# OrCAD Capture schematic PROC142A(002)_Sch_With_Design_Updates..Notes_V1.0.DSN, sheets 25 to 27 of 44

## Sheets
25 24. PHY CLK & LED DRIVER: size C; title: ETHERNET PHY CLOCK BUFFER & LED DRIVER
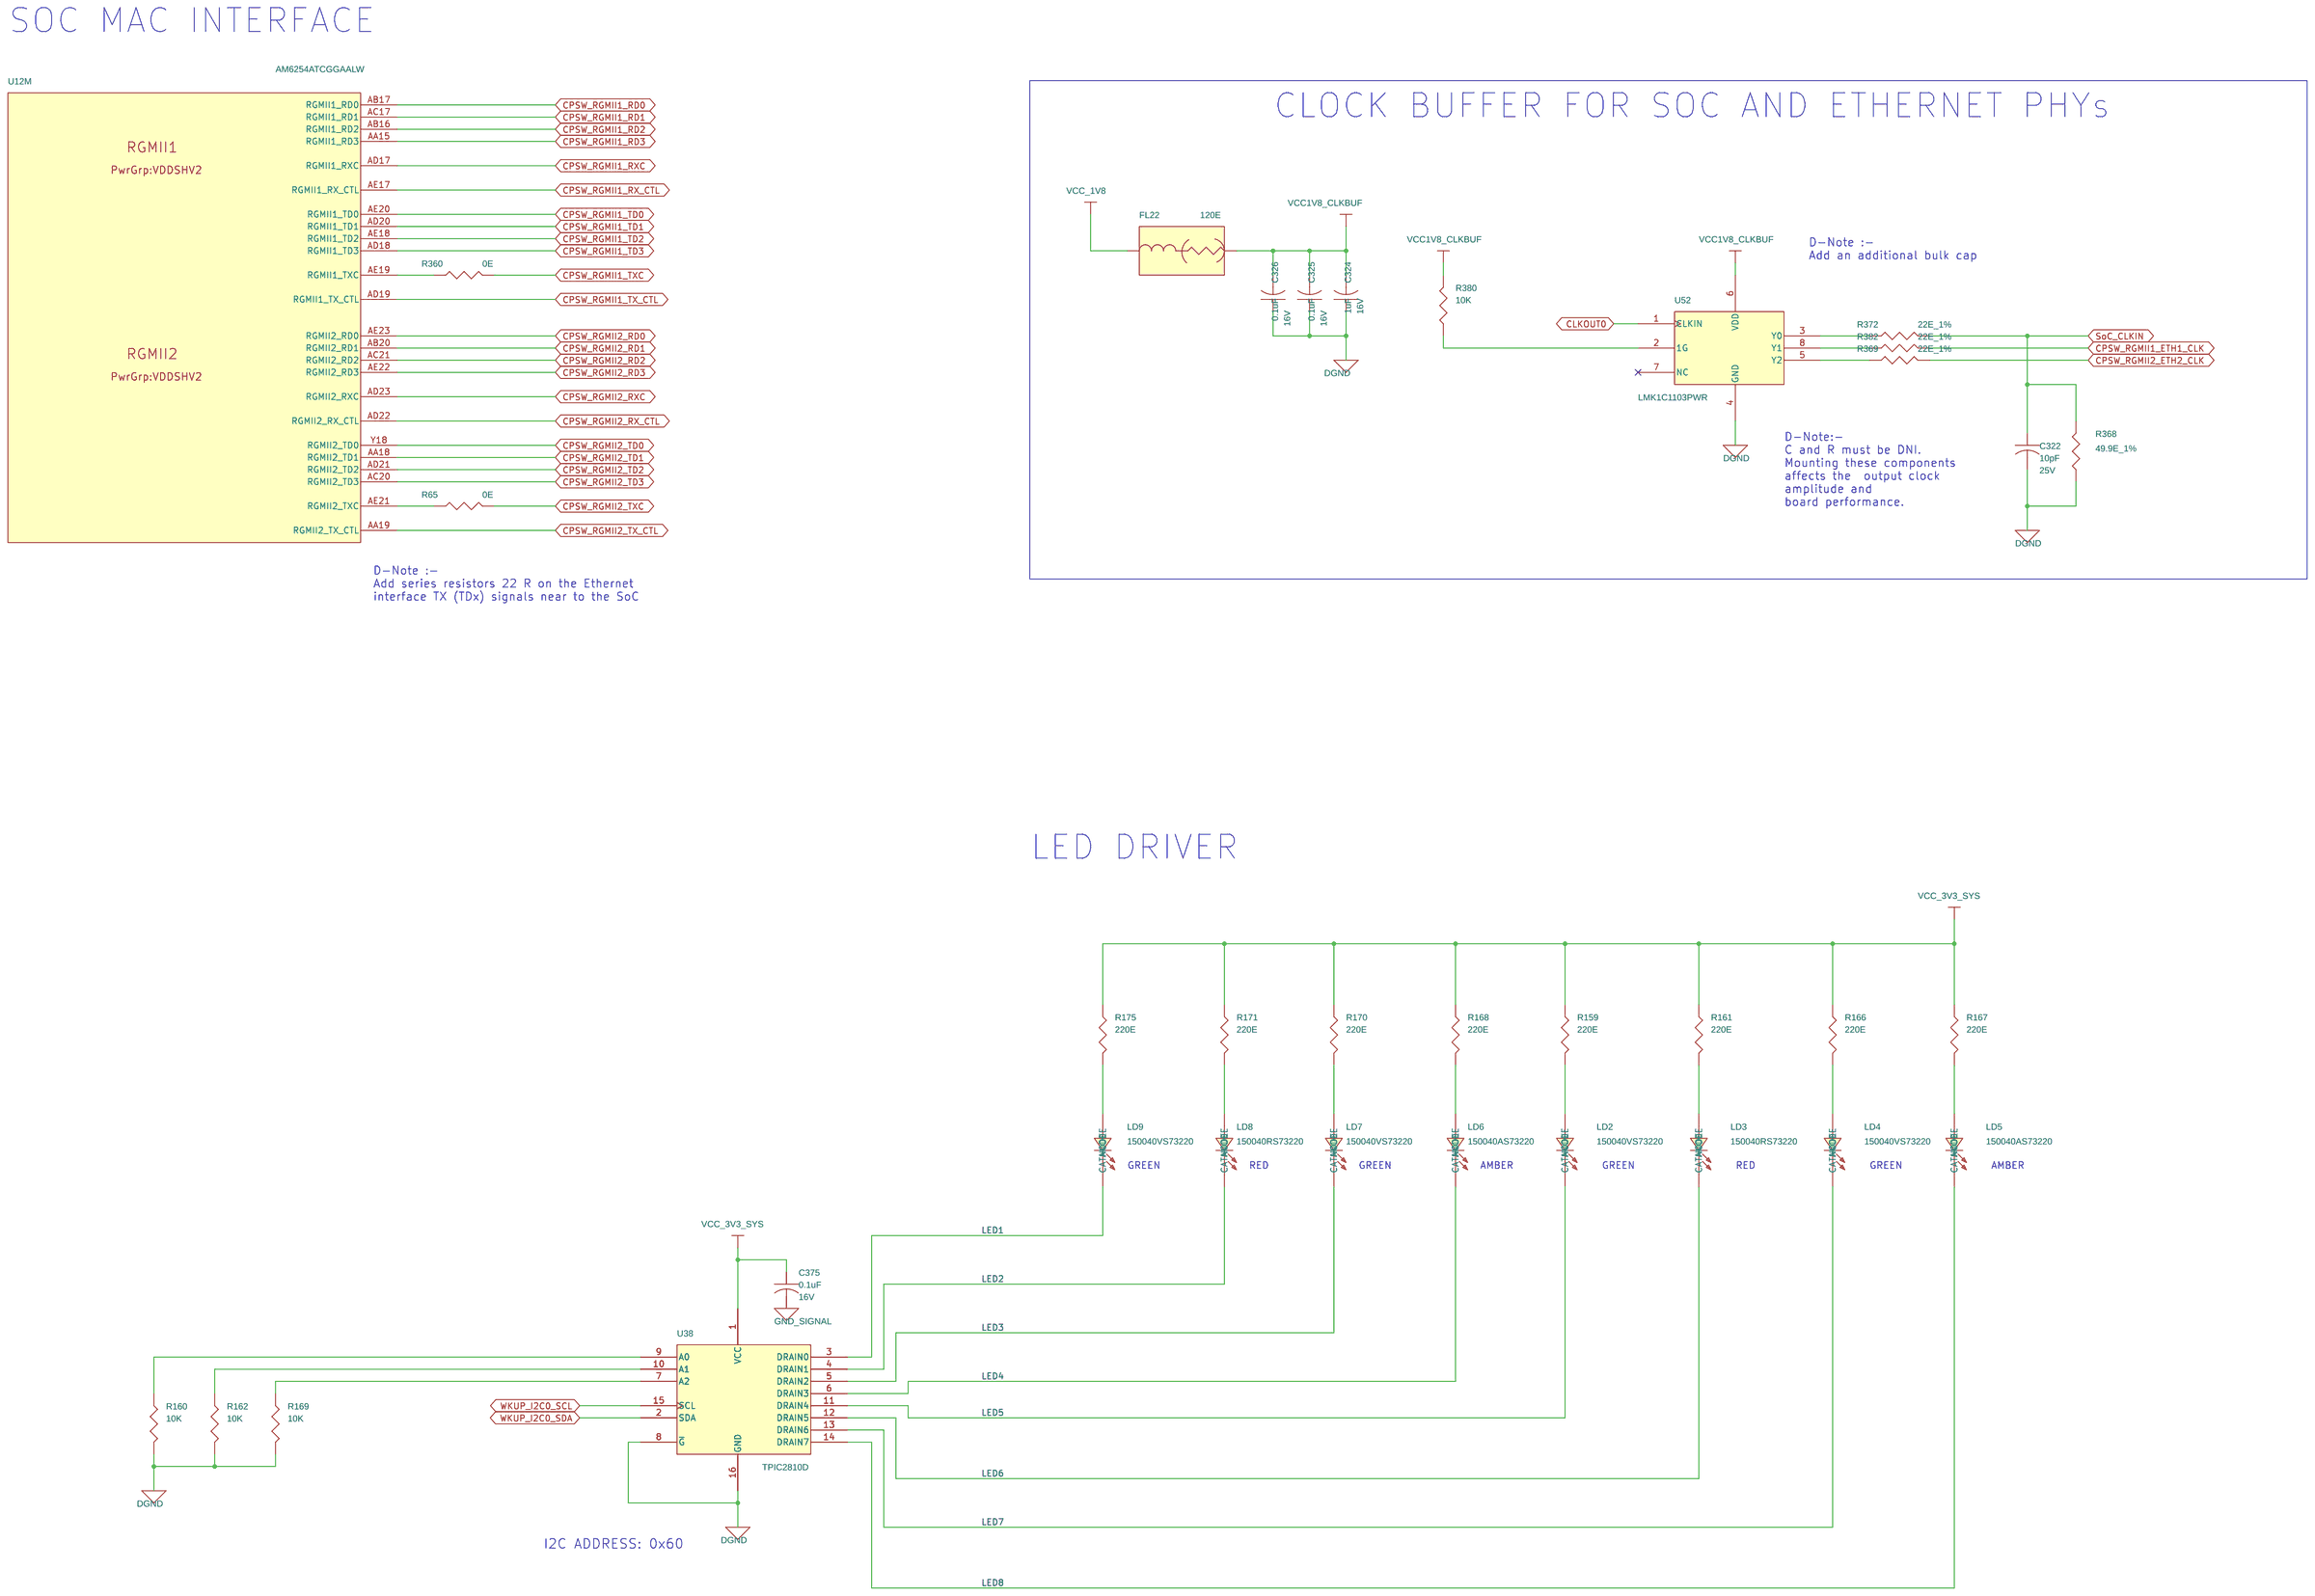
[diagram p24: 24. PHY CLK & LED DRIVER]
26 25. TEST AUTOMATION: size C; title: TEST AUTOMATION
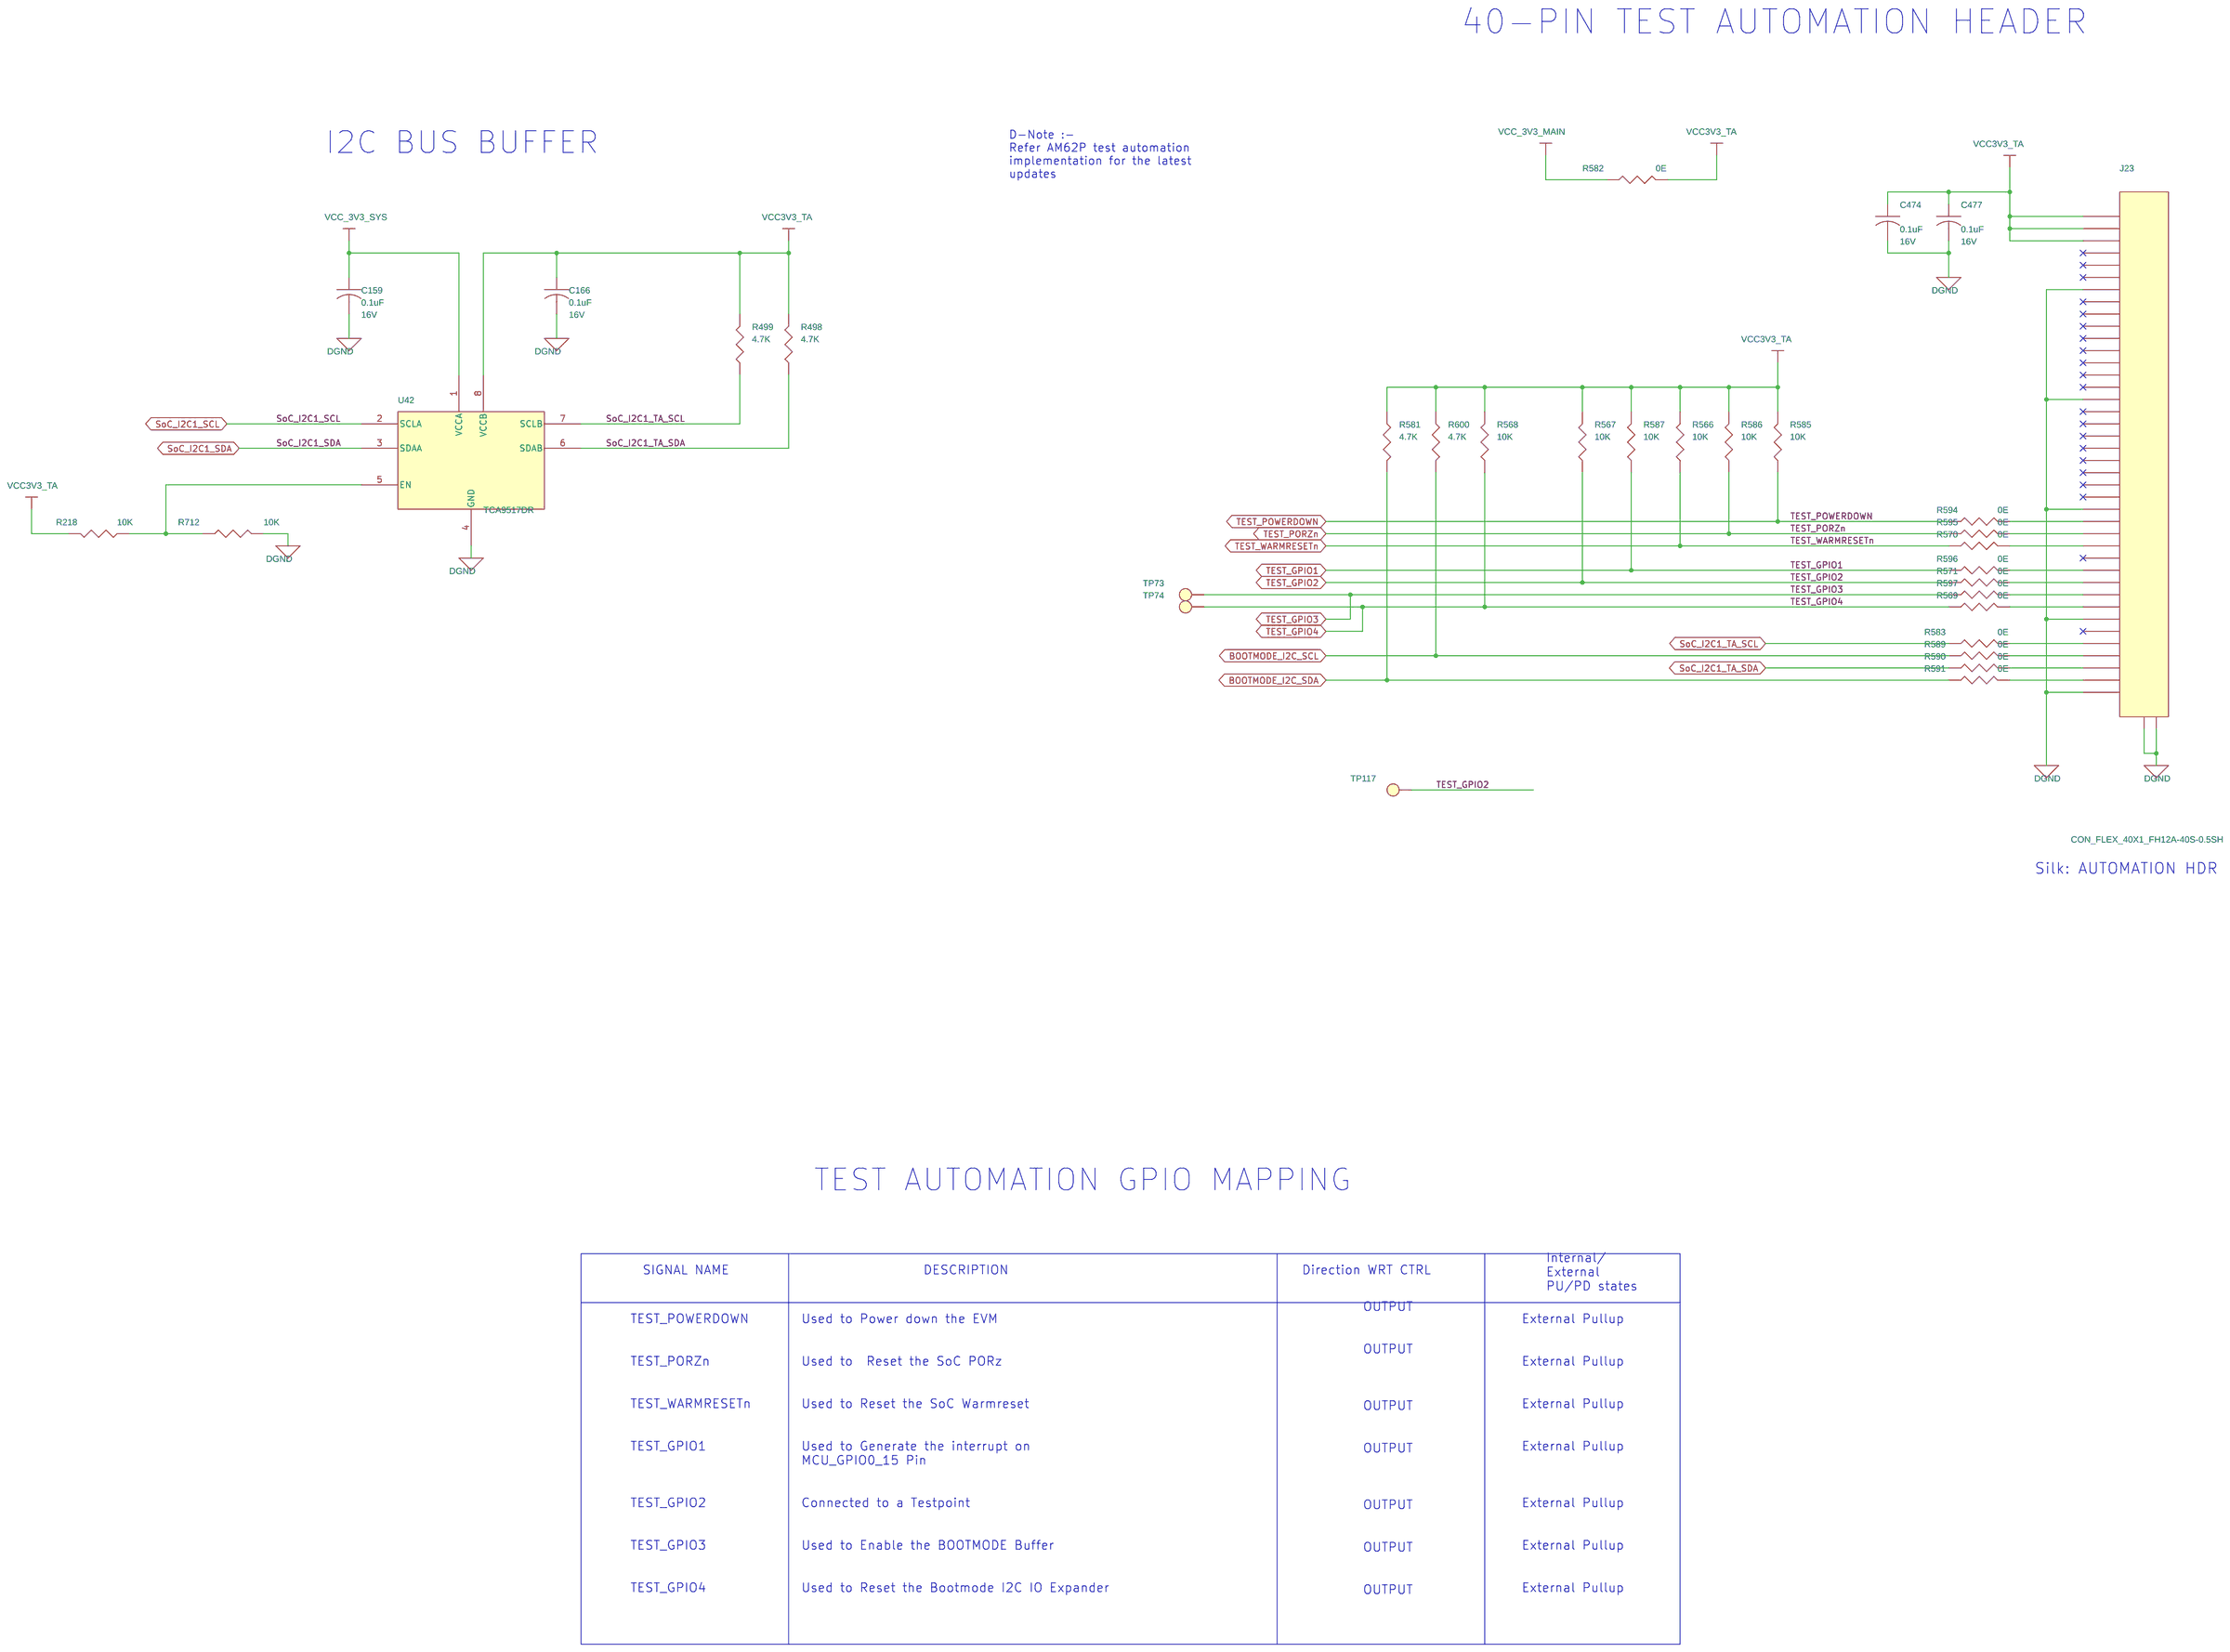
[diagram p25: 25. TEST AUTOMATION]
27 26. BOOT MODE BUFFER & SWITCHES: size C; title: BOOT MODE BUFFER & SWITCHES
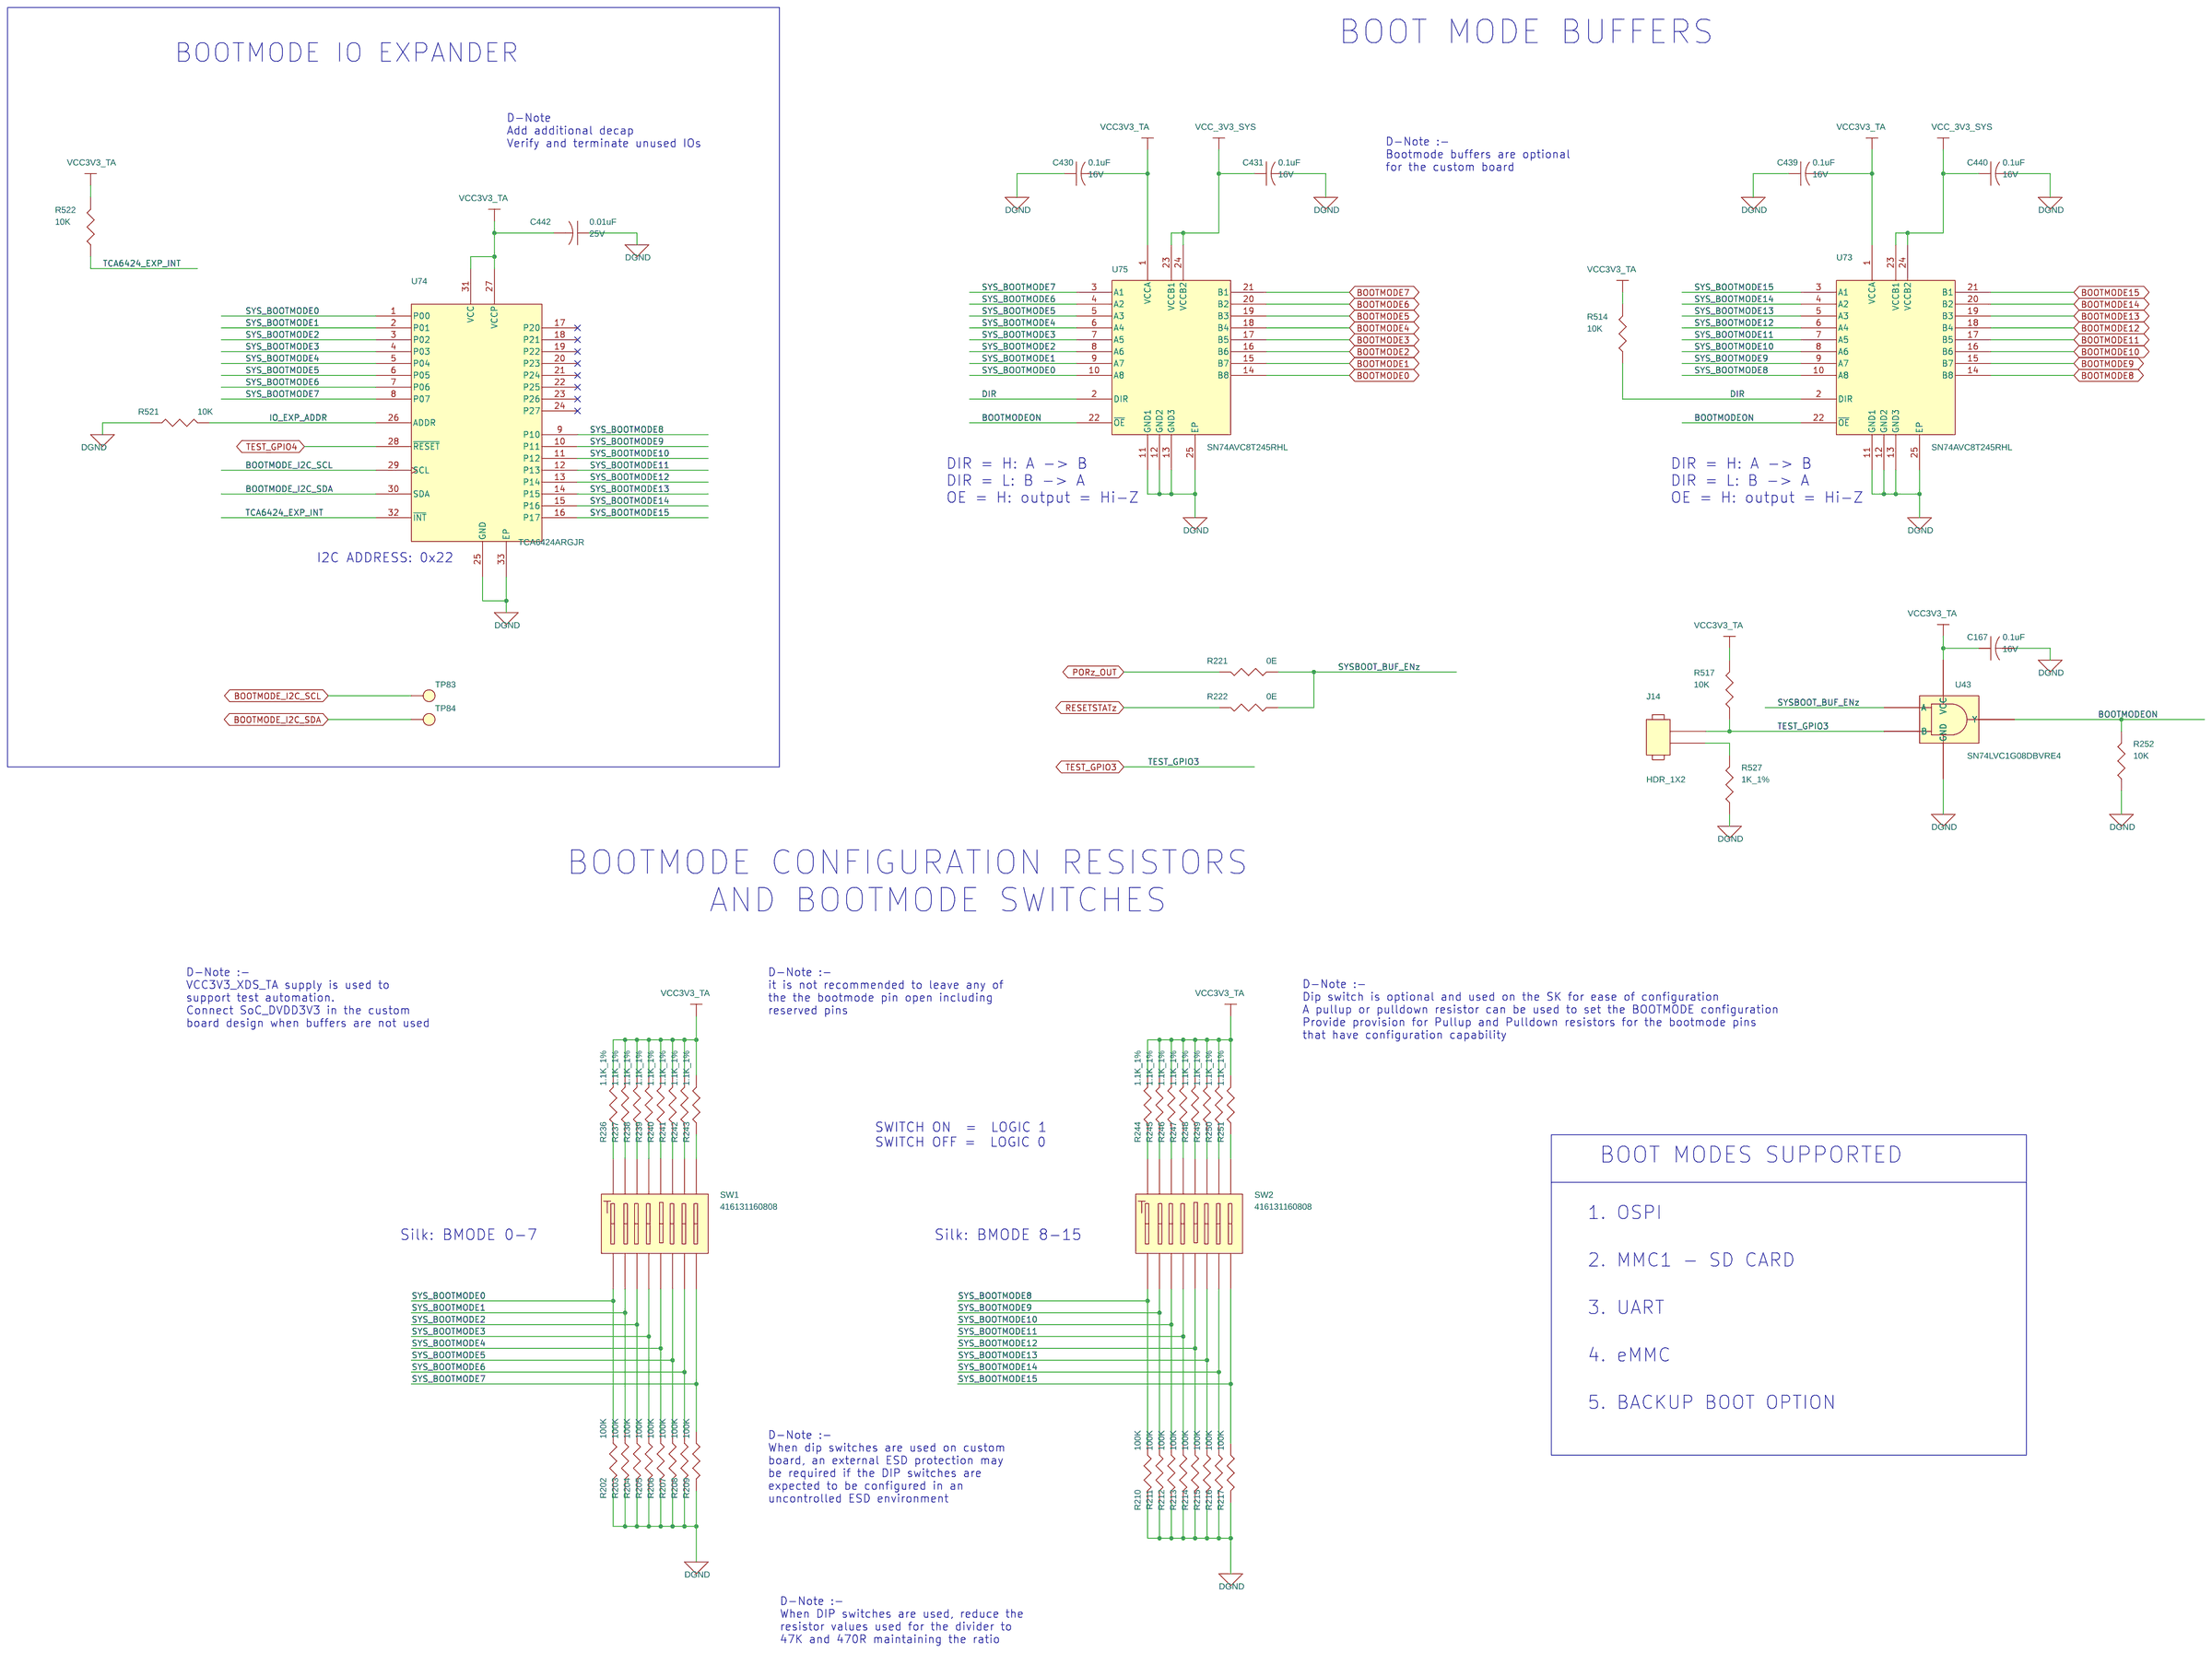
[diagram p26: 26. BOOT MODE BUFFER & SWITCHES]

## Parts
sheet 24. PHY CLK & LED DRIVER
C322  10pF  [CAP0201_0-5]
C324  1uF  [CAP0201_0-5]
C325  0.1uF  [CAP0201_0-5]
C326  0.1uF  [CAP0201_0-5]
C375  0.1uF  [CAP0201_0-5]
FL22  120E  [EMIFIL_BLM15A_0402_0-6]
LD2  150040VS73220  [LED_150040GS73220_40X20_SMD_0-4]
LD3  150040RS73220  [LED_150040GS73220_40X20_SMD_0-4]
LD4  150040VS73220  [LED_150040GS73220_40X20_SMD_0-4]
LD5  150040AS73220  [LED_150040GS73220_40X20_SMD_0-4]
LD6  150040AS73220  [LED_150040GS73220_40X20_SMD_0-4]
LD7  150040VS73220  [LED_150040GS73220_40X20_SMD_0-4]
LD8  150040RS73220  [LED_150040GS73220_40X20_SMD_0-4]
LD9  150040VS73220  [LED_150040GS73220_40X20_SMD_0-4]
R65  0E  [RES0402_0-5]
R159  220E  [RES0402_0-5]
R160  10K  [RES0201_0-5]
R161  220E  [RES0402_0-5]
R162  10K  [RES0201_0-5]
R166  220E  [RES0402_0-5]
R167  220E  [RES0402_0-5]
R168  220E  [RES0402_0-5]
R169  10K  [RES0201_0-5]
R170  220E  [RES0402_0-5]
R171  220E  [RES0402_0-5]
R175  220E  [RES0402_0-5]
R360  0E  [RES0402_0-5]
R368  49.9E_1%  [RES0402_0-5]
R369  22E_1%  [RES0201_0-5]
R372  22E_1%  [RES0201_0-5]
R380  10K  [RES0201_0-5]
R382  22E_1%  [RES0201_0-5]
U38  TPIC2810D  [SOIC16_1-8]
U52  LMK1C1103PWR  [TSSOP8_25-59_125X180_1-2]
sheet 25. TEST AUTOMATION
C159  0.1uF  [CAP0201_0-5]
C166  0.1uF  [CAP0201_0-5]
C474  0.1uF  [CAP0201_0-5]
C477  0.1uF  [CAP0201_0-5]
J23  CON_FLEX_40X1_FH12A-40S-0.5SH  [CON_FLEX40X1_FH12A_S_R_S]
R218  10K  [RES0201_0-5]
R498  4.7K  [RES0201_0-5]
R499  4.7K  [RES0201_0-5]
R566  10K  [RES0201_0-5]
R567  10K  [RES0201_0-5]
R568  10K  [RES0201_0-5]
R569  0E  [RES0402_0-5]
R570  0E  [RES0402_0-5]
R571  0E  [RES0402_0-5]
R581  4.7K  [RES0201_0-5]
R582  0E  [RES0805_0-75]
R583  0E  [RES0402_0-5]
R585  10K  [RES0201_0-5]
R586  10K  [RES0201_0-5]
R587  10K  [RES0201_0-5]
R589  0E  [RES0402_0-5]
R590  0E  [RES0402_0-5]
R591  0E  [RES0402_0-5]
R594  0E  [RES0402_0-5]
R595  0E  [RES0402_0-5]
R596  0E  [RES0402_0-5]
R597  0E  [RES0402_0-5]
R600  4.7K  [RES0201_0-5]
R712  10K  [RES0201_0-5]
TP73  TP20_SMD  [TP20_SMD]
TP74  TP20_SMD  [TP20_SMD]
TP117  TP20_SMD  [TP20_SMD]
U42  TCA9517DR  [SOIC8_1-8]
sheet 26. BOOT MODE BUFFER & SWITCHES
C167  0.1uF  [CAP0201_0-5]
C430  0.1uF  [CAP0201_0-5]
C431  0.1uF  [CAP0201_0-5]
C439  0.1uF  [CAP0201_0-5]
C440  0.1uF  [CAP0201_0-5]
C442  0.01uF  [CAP0201_0-5]
J14  HDR_1X2  [HDR_1X2_90120-0122_S_T_5-6]
R202  100K  [RES0201_0-5]
R203  100K  [RES0201_0-5]
R204  100K  [RES0201_0-5]
R205  100K  [RES0201_0-5]
R206  100K  [RES0201_0-5]
R207  100K  [RES0201_0-5]
R208  100K  [RES0201_0-5]
R209  100K  [RES0201_0-5]
R210  100K  [RES0201_0-5]
R211  100K  [RES0201_0-5]
R212  100K  [RES0201_0-5]
R213  100K  [RES0201_0-5]
R214  100K  [RES0201_0-5]
R215  100K  [RES0201_0-5]
R216  100K  [RES0201_0-5]
R217  100K  [RES0201_0-5]
R221  0E  [RES0201_0-5]
R222  0E  [RES0402_0-5]
R236  1.1K_1%  [RES0201_0-5]
R237  1.1K_1%  [RES0201_0-5]
R238  1.1K_1%  [RES0201_0-5]
R239  1.1K_1%  [RES0201_0-5]
R240  1.1K_1%  [RES0201_0-5]
R241  1.1K_1%  [RES0201_0-5]
R242  1.1K_1%  [RES0201_0-5]
R243  1.1K_1%  [RES0201_0-5]
R244  1.1K_1%  [RES0201_0-5]
R245  1.1K_1%  [RES0201_0-5]
R246  1.1K_1%  [RES0201_0-5]
R247  1.1K_1%  [RES0201_0-5]
R248  1.1K_1%  [RES0201_0-5]
R249  1.1K_1%  [RES0201_0-5]
R250  1.1K_1%  [RES0201_0-5]
R251  1.1K_1%  [RES0201_0-5]
R252  10K  [RES0201_0-5]
R514  10K  [RES0201_0-5]
R517  10K  [RES0201_0-5]
R521  10K  [RES0201_0-5]
R522  10K  [RES0201_0-5]
R527  1K_1%  [RES0402_0-5]
SW1  416131160808  [SW16_416131160808_460X230_SMD_2-7]
SW2  416131160808  [SW16_416131160808_460X230_SMD_2-7]
TP83  TP20_SMD  [TP20_SMD]
TP84  TP20_SMD  [TP20_SMD]
U43  SN74LVC1G08DBVRE4  [SOT23-5]
U73  SN74AVC8T245RHL  [QFN24_19-68_220X140_1]
U74  TCA6424ARGJR  [QFN32_19-68_200X200]
U75  SN74AVC8T245RHL  [QFN24_19-68_220X140_1]
sheet 42. OSCILLATOR
U12  AM6254ATCGGAALW  [BGA425_19-68_510X510_0-7]  (sections A,B,C,D,E,F,G,H,I,J,K,L,M,N,O,P,Q,R)

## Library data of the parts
C322 = CAP: CAP CERAMIC 10pF 25V 5% HI-Q C0G(NP0) 0201; Chkd/date: VASANTHA/081216; Crtd /date: MANIRAJA/081216; Custom_Duty: 15%; Customs_HS_Code: 85322990; Distributor_name: DIGIKEY; Distributor_part_number: 490-13312-1-ND; Footprint Path: Y:\MIS_DATABASE\Library\ALTIUM_TOOL\PCB_FOOTPRINTS\Altium_Footprint_Lib.PcbLib; Height: 0.33MM; Library Path: Y:\MIS_DATABASE\Library\ALTIUM_TOOL\SCHEMATICS_PARTS\MS_DISCRETE_Library.schlib; Mfr_name: MURATA; Mfr_part_number: GJM0335C1E100JB01D; Mistral Part No: 120016120010-R; Package: 0201; Part_type: CAPACITORS\CERAMIC; Project: OCTBTS5200; RoHS: RoHS; Temperature: -55°C+125°C; Tolerance: 5%; Voltage: 25V; Wattage: NA; Weight: 0.33mg; Datasheet: Y:\MIS_DATABASE\DATASHEETS\CAPACITORS\MURATA-GXX-SER_NOV17.PDF
C324 = CAP: CAP CERAMIC 1uF 16V 20% X5R 0201; Chkd/date: MANIRAJA/300520; Crtd /date: ALVY/260520; Custom_Duty: 15%; Customs_HS_Code: 85322990; Distributor_name: DIGIKEY; Distributor_part_number: 490-18654-1-ND; Footprint Path: Y:\MIS_DATABASE\Library\ALTIUM_TOOL\PCB_FOOTPRINTS\Altium_Footprint_Lib.PcbLib; Height: 0.39MM; Library Path: Y:\MIS_DATABASE\Library\ALTIUM_TOOL\SCHEMATICS_PARTS\MS_DISCRETE_Library.schlib; Mfr_name: MURATA; Mfr_part_number: GRM033R61C105ME15D; Mistral Part No: 120018090038-R; Package: 0201; Part_type: CAPACITORS\CERAMIC; Project: QCS610_NANOSOM; RoHS: RoHS; Temperature: -55°C+85°C; Tolerance: 20%; Voltage: 16V; Wattage: NA; Weight: 0.33mg; Datasheet: Y:\MIS_DATABASE\DATASHEETS\CAPACITORS\GRM033R61C105ME15.PDF
C159 C166 C167 C325 C326 C375 C430 C431 C439 C440 C474 C477 = CAP: CAP CERAMIC 0.1uF 16V 10% X5R 0201; Alt_Mfr_name: YAGEO AMERICA; Alt_Mfr_part_number: CC0402KRX5R8BB104; Chkd/date: MANIRAJA/230118; Crtd /date: MANIRAJA/230118; Custom_Duty: 15%; Customs_HS_Code: 85322990; Distributor_name: DIGIKEY; Distributor_part_number: 490-14305-1-ND; Footprint Path: Y:\MIS_DATABASE\Library\ALTIUM_TOOL\PCB_FOOTPRINTS\Altium_Footprint_Lib.PcbLib; Height: 0.33MM; Library Path: Y:\MIS_DATABASE\Library\ALTIUM_TOOL\SCHEMATICS_PARTS\MS_DISCRETE_Library.schlib; Mfr_name: MURATA; Mfr_part_number: GRM033R61C104KE14D; Mistral Part No: 120009030072-R; Package: 0201; Part_type: CAPACITORS\CERAMIC; Project: TI_MAXIE_CPB; RoHS: RoHS; Temperature: -55°C+85°C; Tolerance: 10%; Voltage: 16V; Wattage: NA; Weight: 0.33mg; Datasheet: Y:\MIS_DATABASE\DATASHEETS\CAPACITORS\GRM033R61C104KE14.PDF
FL22 = EMIFILTER_IND: IND FERRITE BEAD CHIP 120E 2A 0402; Chkd/date: NAVEED/241114; Crtd /date: USMAN/170613; Custom_Duty: 24%; Customs_HS_Code: 85369090; Distributor_name: DIGIKEY; Distributor_part_number: 490-9656-1-ND; Footprint Path: Y:\MIS_DATABASE\Library\ALTIUM_TOOL\PCB_FOOTPRINTS\Altium_Footprint_Lib.PcbLib; Height: 0.55MM; Library Path: Y:\MIS_DATABASE\Library\ALTIUM_TOOL\SCHEMATICS_PARTS\MS_FILTER_Library.schlib; Mfr_name: MURATA; Mfr_part_number: BLM15PX121SN1D; Mistral Part No: 130013060022-R; Package: 0402; Part_type: INDUCTOR; Project: GEN_3-8; RoHS: RoHS; Temperature: -55°C+125°C; Tolerance: 25%; Voltage: NA; Wattage: NA; Weight: 1mg; Datasheet: Y:\MIS_DATABASE\DATASHEETS\DISCRETES\INDUCTORS\BLM15-SN1-SER.PDF
LD2 LD4 LD7 LD9 = DIODE_LED: DIODE LED BRIGHT GREEN SMD; Chkd/date: MANIRAJA/261120; Crtd /date: ALVY/261120; Custom_Duty: 24%; Customs_HS_Code: 85439000; Distributor_name: DIGIKEY; Distributor_part_number: 732-13425-1-ND; Footprint Path: Y:\MIS_DATABASE\Library\ALTIUM_TOOL\PCB_FOOTPRINTS\Altium_Footprint_Lib.PcbLib; Height: 0.35MM; Library Path: Y:\MIS_DATABASE\Library\ALTIUM_TOOL\SCHEMATICS_PARTS\MS_OPTO_Library.schlib; Mfr_name: WURTH ELECTRONIK; Mistral Part No: 130020110071-R; Package: SMD; Part_type: OPTO\LED; Project: AM64X_SKEVM; RoHS: RoHS; Temperature: -40°C+85°C; Tolerance: NA; Voltage: NA; Wattage: NA; Weight: 29.3mg; Datasheet: Y:\MIS_DATABASE\DATASHEETS\DISCRETES\LEDS\150040VS73220.PDF
LD3 LD8 = DIODE_LED: DIODE LED RED SMD; Chkd/date: MANIRAJA/100920; Crtd /date: ALVY/100920; Custom_Duty: 24%; Customs_HS_Code: 85439000; Distributor_name: DIGIKEY; Distributor_part_number: 732-13422-1-ND; Footprint Path: Y:\MIS_DATABASE\Library\ALTIUM_TOOL\PCB_FOOTPRINTS\Altium_Footprint_Lib.PcbLib; Height: 0.35MM; Library Path: Y:\MIS_DATABASE\Library\ALTIUM_TOOL\SCHEMATICS_PARTS\MS_OPTO_Library.schlib; Mfr_name: WURTH ELECTRONICS; Mistral Part No: 130020090020-R; Package: SMD; Part_type: OPTO\LED; Project: AM64X_SKEVM; RoHS: RoHS; Temperature: -40°C+85°C; Tolerance: NA; Voltage: NA; Wattage: NA; Weight: 29.3mg; Datasheet: Y:\MIS_DATABASE\DATASHEETS\DISCRETES\LEDS\150040RS73220.PDF
LD5 LD6 = DIODE_LED: DIODE LED AMBER SMD; Chkd/date: MANIRAJA/100920; Crtd /date: ALVY/100920; Custom_Duty: 24%; Customs_HS_Code: 85439000; Distributor_name: DIGIKEY; Distributor_part_number: 732-13423-1-ND; Footprint Path: Y:\MIS_DATABASE\Library\ALTIUM_TOOL\PCB_FOOTPRINTS\Altium_Footprint_Lib.PcbLib; Height: 0.35MM; Library Path: Y:\MIS_DATABASE\Library\ALTIUM_TOOL\SCHEMATICS_PARTS\MS_OPTO_Library.schlib; Mfr_name: WURTH ELECTRONICS; Mistral Part No: 130020090022-R; Package: SMD; Part_type: OPTO\LED; Project: AM64X_SKEVM; RoHS: RoHS; Temperature: -40°C+85°C; Tolerance: NA; Voltage: NA; Wattage: NA; Weight: 29.3mg; Datasheet: Y:\MIS_DATABASE\DATASHEETS\DISCRETES\LEDS\150040AS73220.PDF
R65 R360 = RESISTOR: RES 0E 1/16W JUMPER 0402; Chkd/date: VASANTHA/201216; Crtd /date: MUDDU/190810; Custom_Duty: 15%; Customs_HS_Code: 85332119; Distributor_name: DIGIKEY; Distributor_part_number: 541-0.0JCT-ND; Footprint Path: Y:\MIS_DATABASE\Library\ALTIUM_TOOL\PCB_FOOTPRINTS\Altium_Footprint_Lib.PcbLib; Height: 0.40MM; Library Path: Y:\MIS_DATABASE\Library\ALTIUM_TOOL\SCHEMATICS_PARTS\MS_DISCRETE_Library.schlib; Mfr_name: VISHAY; Mfr_part_number: CRCW04020000Z0ED; Mistral Part No: 110010080019-R; Package: 0402; Part_type: RESISTORS\FIXED; Project: PB_BUGBASE; RoHS: RoHS; SIGNAL_MODEL: RESISTOR_RES0402_0-5_0E_0E; Temperature: -55°C+155°C; Tolerance: NA; Voltage: NA; Wattage: 1/16W; Weight: 0.65mg; Datasheet: Y:\MIS_DATABASE\DATASHEETS\RESISTORS\CRCW0603.PDF
R159 R161 R166-R168 R170 R171 R175 = RESISTOR: RES 220E 1/10W 5% 0402; Chkd/date: VASANTHA/291216; Crtd /date: GEETHA/260406; Custom_Duty: 15%; Customs_HS_Code: 85332119; Distributor_name: DIGIKEY; Distributor_part_number: P220JCT-ND; Footprint Path: Y:\MIS_DATABASE\Library\ALTIUM_TOOL\PCB_FOOTPRINTS\Altium_Footprint_Lib.PcbLib; Height: 0.40MM; Library Path: Y:\MIS_DATABASE\Library\ALTIUM_TOOL\SCHEMATICS_PARTS\MS_DISCRETE_Library.schlib; Manufacturer: PANASONIC-ECG; Mfr_name: PANASONIC-ECG; Mfr_part_number: ERJ-2GEJ221X; Mistral Part No: 110009030506-R; Package: 0402; Part_type: RESISTORS\FIXED; Project: RED EYE; RoHS: RoHS; Temperature: -55°C+155°C; Tolerance: 5%; Voltage: NA; Wattage: 1/10W; Weight: 0.8mg; Datasheet: Y:\MIS_DATABASE\DATASHEETS\RESISTORS\PAN-ERJSER_NOV17.PDF
R160 R162 R169 R218 R252 R380 R514 R517 R521 R522 R566-R568 R585-R587 R712 = RESISTOR: RES 10K 1/20W 5% 0201; Chkd/date: MANIRAJA/050517; Crtd /date: MANIRAJA/050517; Custom_Duty: 15%; Customs_HS_Code: 85332119; Distributor_name: DIGIKEY; Distributor_part_number: 311-10KNCT-ND; Footprint Path: Y:\MIS_DATABASE\Library\ALTIUM_TOOL\PCB_FOOTPRINTS\Altium_Footprint_Lib.PcbLib; Height: 0.26MM; Library Path: Y:\MIS_DATABASE\Library\ALTIUM_TOOL\SCHEMATICS_PARTS\MS_DISCRETE_Library.schlib; Mfr_name: YAGEO AMERICA; Mfr_part_number: RC0201JR-0710KL; Mistral Part No: 110010070051-R; Package: 0201; Part_type: RESISTORS\FIXED; Project: GOLDEN-I LITE; RoHS: RoHS; Temperature: -55°C+125°C; Tolerance: 5%; Voltage: NA; Wattage: 1/20W; Weight: 0.17mg; Datasheet: Y:\MIS_DATABASE\DATASHEETS\RESISTORS\RCXXXXL-SER_MAR18.PDF
R368 = RESISTOR: RES 49.9E 1/16W 1% 0402; Chkd/date: MANIRAJA/210519; Crtd /date: MANIRAJA/210519; Custom_Duty: 15%; Customs_HS_Code: 85332119; Distributor_name: DIGIKEY; Distributor_part_number: 541-3967-1-ND; Footprint Path: Y:\MIS_DATABASE\Library\ALTIUM_TOOL\PCB_FOOTPRINTS\Altium_Footprint_Lib.PcbLib; Height: 0.35MM; Library Path: Y:\MIS_DATABASE\Library\ALTIUM_TOOL\SCHEMATICS_PARTS\MS_DISCRETE_Library.schlib; Mfr_name: VISHAY; Mfr_part_number: CRCW040249R9FKEDC; Mistral Part No: 110009030846-R; Package: 0402; Part_type: RESISTORS\FIXED; Project: RFSU_RFTJ_CARD; RoHS: RoHS; Temperature: -55°C+155°C; Tolerance: 1%; Voltage: NA; Wattage: 1/16W; Weight: 0.65mg; Datasheet: Y:\MIS_DATABASE\DATASHEETS\RESISTORS\CRCW_C-SER.PDF
R369 R372 R382 = RESISTOR: RES 22E 1/20W 1% 0201; Chkd/date: MAZHAR/140709; Crtd /date: MAZHAR/220807; Custom_Duty: 15%; Customs_HS_Code: 85332119; Distributor_name: DIGIKEY; Distributor_part_number: P22.0ABCT-ND; Footprint Path: Y:\MIS_DATABASE\Library\ALTIUM_TOOL\PCB_FOOTPRINTS\Altium_Footprint_Lib.PcbLib; Height: 0.26MM; Library Path: Y:\MIS_DATABASE\Library\ALTIUM_TOOL\SCHEMATICS_PARTS\MS_DISCRETE_Library.schlib; Mfr_name: PANASONIC-ECG; Mfr_part_number: ERJ-1GEF22R0C; Mistral Part No: 110009030522-R; Package: 0201; Part_type: RESISTORS\FIXED; Project: V8TS; RoHS: RoHS; Temperature: -55°C+125°C; Tolerance: 1%; Voltage: NA; Wattage: 1/20W; Weight: 0.15mg; Datasheet: Y:\MIS_DATABASE\DATASHEETS\RESISTORS\PAN-ERJSER_NOV17.PDF
U38 = TPIC2810D_SOIC16: IC 8-BIT LED DRIVER WITH I2C INTERFACE SOIC16; Chkd/date: MANIRAJA/230817; Crtd /date: MANIRAJA/220817; Custom_Duty: 15%; Customs_HS_Code: 85423100; Distributor_name: DIGIKEY; Distributor_part_number: 296-13746-5-ND; Height: 1.75MM; Mfr_name: TEXAS INSTRUMENTS; Mistral Part No: 141017080026-R; Package: SOIC16; Part_type: ICS\INTERFACE; Project: TI_MAXIE_CPB; RoHS: RoHS; Temperature: -40°C+125°C; Tolerance: NA; Voltage: NA; Wattage: NA; Weight: NA; Datasheet: Y:\MIS_DATABASE\DATASHEETS\ICS\INTERFACE\TPIC2810D.PDF
U52 = LMK1C1103_TSSOP8: IC 3-CHANNEL LVCMOS CLOCK BUFFER TSSOP8; Chkd/date: MANIRAJA/080920; Crtd /date: ALVY/070920; Custom_Duty: 15%; Customs_HS_Code: 85423100; Distributor_name: DIGIKEY; Distributor_part_number: 296-LMK1C1103PWRCT-ND; Footprint Path: Y:\MIS_DATABASE\Library\ALTIUM_TOOL\PCB_FOOTPRINTS\Altium_Footprint_Lib.PcbLib; Height: 1.20MM; Library Path: Y:\MIS_DATABASE\Library\ALTIUM_TOOL\SCHEMATICS_PARTS\MS_COMBINATIONAL_Library.schlib; Mfr_name: TEXAS INSTRUMENTS; Mistral Part No: 141020090002-R; Package: TSSOP8; Part_type: ICS\DIGITAL\COMBINATIONAL; Project: AM64X_SKEVM; RoHS: RoHS; Temperature: -40°C+125°C; Tolerance: NA; Voltage: NA; Wattage: NA; Weight: 34.1mg; Datasheet: Y:\MIS_DATABASE\DATASHEETS\ICS\DIGITAL\COMBINATIONAL\LMK1C110X.PDF
J23 = CON_FLEX_40X1_FH12A-40S-0.5SH: CON FPC 40X1 0.50MM PITCH RT TOP SMD; Chkd/date: SHREESHAIL/201106; Crtd /date: MAZHAR/171106; Custom_Duty: 24%; Customs_HS_Code: 85369090; Distributor_name: DIGIKEY; Distributor_part_number: HFK40CT-ND; Height: 2.00MM; Mfr_name: HIROSE ELECTRIC EUROPE; Mfr_part_number: FH12A-40S-0.5SH(55); Mistral Part No: 150009030176-R; Package: SMD; Part_type: CONNECTOR\FPC; Project: PMP LCD BOARD; Datasheet: Y:\MIS_DATABASE\DATASHEETS\CONNECTORS\FH12SERIES.PDF
R498 R499 R581 R600 = RESISTOR: RES 4.7K 1/20W 5% 0201; Chkd/date: MANIRAJA/200921; Crtd /date: ALVY/200921; Custom_Duty: 15%; Customs_HS_Code: 85332119; Distributor_name: DIGIKEY; Distributor_part_number: 311-4.7KNCT-ND; Footprint Path: Y:\MIS_DATABASE\Library\ALTIUM_TOOL\PCB_FOOTPRINTS\Altium_Footprint_Lib.PcbLib; Height: 0.26MM; Library Path: Y:\MIS_DATABASE\Library\ALTIUM_TOOL\SCHEMATICS_PARTS\MS_DISCRETE_Library.schlib; Mfr_name: YAGEO AMERICA; Mfr_part_number: RC0201JR-074K7L; Mistral Part No: 110021090007-R; Package: 0201; Part_type: RESISTORS\FIXED; Project: TI_AM62x SKEVM_BRD; RoHS: RoHS; Temperature: -55°C+125°C; Tolerance: 5%; Voltage: NA; Wattage: 1/20W; Weight: 0.17mg; Datasheet: Y:\MIS_DATABASE\DATASHEETS\RESISTORS\RCXXXXL-SER_MAR18.PDF
R222 R569-R571 R583 R589-R591 R594-R597 = RESISTOR: RES 0E 1/16W JUMPER 0402; Chkd/date: VASANTHA/201216; Crtd /date: MUDDU/190810; Custom_Duty: 15%; Customs_HS_Code: 85332119; Distributor_name: DIGIKEY; Distributor_part_number: 541-0.0JCT-ND; Footprint Path: Y:\MIS_DATABASE\Library\ALTIUM_TOOL\PCB_FOOTPRINTS\Altium_Footprint_Lib.PcbLib; Height: 0.40MM; Library Path: Y:\MIS_DATABASE\Library\ALTIUM_TOOL\SCHEMATICS_PARTS\MS_DISCRETE_Library.schlib; Mfr_name: VISHAY; Mfr_part_number: CRCW04020000Z0ED; Mistral Part No: 110010080019-R; Package: 0402; Part_type: RESISTORS\FIXED; Project: PB_BUGBASE; RoHS: RoHS; Temperature: -55°C+155°C; Tolerance: NA; Voltage: NA; Wattage: 1/16W; Weight: 0.65mg; Datasheet: Y:\MIS_DATABASE\DATASHEETS\RESISTORS\CRCW0603.PDF
R582 = RESISTOR: RES 0E 1/8W 5% 0805; Chkd/date: VASANTHA/130416; Crtd /date: JEBRAN/020316; Custom_Duty: 15%; Customs_HS_Code: 85332119; Distributor_name: DIGIKEY; Distributor_part_number: 311-0.0ARCT-ND; Footprint Path: Y:\MIS_DATABASE\Library\ALTIUM_TOOL\PCB_FOOTPRINTS\Altium_Footprint_Lib.PcbLib; Height: 0.60MM; Library Path: Y:\MIS_DATABASE\Library\ALTIUM_TOOL\SCHEMATICS_PARTS\MS_DISCRETE_Library.schlib; Mfr_name: YAGEO AMERICA; Mfr_part_number: RC0805JR-070RL; Mistral Part No: 110009030074-R; Package: 0805; Part_type: RESISTORS\FIXED; Project: ZK_BIOMETRIC; RoHS: RoHS; Temperature: -55°C+155°C; Tolerance: 5%; Voltage: NA; Wattage: 1/8W; Weight: 5.5mg; Datasheet: Y:\MIS_DATABASE\DATASHEETS\RESISTORS\RCXXXXL-SER_MAR18.PDF
TP73 TP74 TP83 TP84 TP117 = TESTPOINT: TESTPOINT CIR 20 SMD; Chkd/date: SHREESHAIL/171006; Crtd /date: MAZHAR/171006; Custom_Duty: NA; Customs_HS_Code: NA; Distributor_name: NA; Distributor_part_number: NA; Footprint Path: Y:\MIS_DATABASE\Library\ALTIUM_TOOL\PCB_FOOTPRINTS\Altium_Footprint_Lib.PcbLib; Height: NA; Library Path: Y:\MIS_DATABASE\Library\ALTIUM_TOOL\SCHEMATICS_PARTS\MS_DISCRETE_Library.schlib; MECHANICAL 3D STEP FILE: NA; Mfr_name: LOCAL; Mistral Part No: NA; Package: SMD; Project: BT MODULE_CSRBC04; RoHS: NA; Temperature: NA; Tolerance: NA; Voltage: NA; Wattage: NA; Weight: NA; Datasheet: NA
U42 = TCA9517DGKR_VSSOP8: IC 2-CHANNEL BI-DIR LEVEL-SHIFTING I2C BUS REPEATER SOIC8; Chkd/date: MANIRAJA/171121; Crtd /date: ALVY/161121; Custom_Duty: 15%; Customs_HS_Code: 85423100; Distributor_name: DIGIKEY; Distributor_part_number: 296-39221-1-ND; Footprint Path: Y:\MIS_DATABASE\Library\ALTIUM_TOOL\PCB_FOOTPRINTS\Altium_Footprint_Lib.PcbLib; Height: 1.75MM; Library Path: Y:\MIS_DATABASE\Library\ALTIUM_TOOL\SCHEMATICS_PARTS\MS_MISCINTERFACE_Library.schlib; Mfr_name: TEXAS INSTRUMENTS; Mistral Part No: 141021110017-R; Package: SOIC8; Part_type: ICS\INTERFACE\LEVEL TRANSLATOR; Project: EXCITER MULTI-CH RX UNIT; RoHS: RoHS; Temperature: -40°C+85°C; Tolerance: NA; Voltage: NA; Wattage: NA; Weight: 540mg; Datasheet: Y:\MIS_DATABASE\DATASHEETS\ICS\INTERFACE\TCA9517.PDF
C442 = CAP: CAP CERAMIC 0.01uF 25V 10% X5R 0201; Chkd/date: MANIRAJA/230118; Crtd /date: MANIRAJA/230118; Custom_Duty: 15%; Customs_HS_Code: 85322990; Distributor_name: DIGIKEY; Distributor_part_number: GRM033R61E103KA12J-ND; Footprint Path: Y:\MIS_DATABASE\Library\ALTIUM_TOOL\PCB_FOOTPRINTS\Altium_Footprint_Lib.PcbLib; Height: 0.33MM; Library Path: Y:\MIS_DATABASE\Library\ALTIUM_TOOL\SCHEMATICS_PARTS\MS_DISCRETE_Library.schlib; Mfr_name: MURATA; Mfr_part_number: GRM033R61E103KA12J; Mistral Part No: 120018010007-R; Package: 0201; Part_type: CAPACITORS\CERAMIC; Project: TI_MAXIE_CPB; RoHS: RoHS; Temperature: -55°C+85°C; Tolerance: 10%; Voltage: 25V; Wattage: NA; Weight: 0.33mg; Datasheet: Y:\MIS_DATABASE\DATASHEETS\CAPACITORS\GRM033R61E103KA12.PDF
J14 = HEADER_2X1: CON HDR 1X2 2.54MM PITCH ST TH; Chkd/date: NAVEED/210714; Crtd /date: USMAN/031012; Custom_Duty: 24%; Customs_HS_Code: 85369090; Distributor_name: DIGIKEY; Distributor_part_number: WM8072-ND; Footprint Path: Y:\MIS_DATABASE\Library\ALTIUM_TOOL\PCB_FOOTPRINTS\Altium_Footprint_Lib.PcbLib; Height: 5.60MM; Library Path: Y:\MIS_DATABASE\Library\ALTIUM_TOOL\SCHEMATICS_PARTS\MS_CONNECTOR_Library.schlib; Mfr_name: MOLEX; Mfr_part_number: 90120-0122; Mistral Part No: 150012100005-R; Package: THRU-HOLE; Part_type: CONNECTOR\HEADERS; Project: NPOL_FEP; RoHS: RoHS; Temperature: -55°C+125°C; Tolerance: NA; Voltage: NA; Wattage: NA; Weight: 122mg; Datasheet: Y:\MIS_DATABASE\DATASHEETS\CONNECTORS\90120-XX.PDF
R202-R217 = RESISTOR: RES 100K 1/20W 5% 0201; Chkd/date: VASANTHA/061216; Crtd /date: MAZHAR/141105; Custom_Duty: 15%; Customs_HS_Code: 85332119; Distributor_name: DIGIKEY; Distributor_part_number: P100KAGCT-ND; Footprint Path: Y:\MIS_DATABASE\Library\ALTIUM_TOOL\PCB_FOOTPRINTS\Altium_Footprint_Lib.PcbLib; Height: 0.26MM; Library Path: Y:\MIS_DATABASE\Library\ALTIUM_TOOL\SCHEMATICS_PARTS\MS_DISCRETE_Library.schlib; Mfr_name: PANASONIC-ECG; Mfr_part_number: ERJ-1GEJ104C; Mistral Part No: 110009030176-R; Package: 0201; Part_type: RESISTORS\FIXED; Project: J30; RoHS: RoHS; Temperature: -55°C+125°C; Tolerance: 5%; Voltage: NA; Wattage: 1/20W; Weight: 0.15mg; Datasheet: Y:\MIS_DATABASE\DATASHEETS\RESISTORS\PAN-ERJXGE-FEB06.PDF
R221 = RESISTOR: RES 0E 1/20W 5% 0201; Chkd/date: NAVEED/301214; Crtd /date: MUDDU/120710; Custom_Duty: 15%; Customs_HS_Code: 85332119; Distributor_name: DIGIKEY; Distributor_part_number: 311-0.0NCT-ND; Footprint Path: Y:\MIS_DATABASE\Library\ALTIUM_TOOL\PCB_FOOTPRINTS\Altium_Footprint_Lib.PcbLib; Height: 0.26MM; Library Path: Y:\MIS_DATABASE\Library\ALTIUM_TOOL\SCHEMATICS_PARTS\MS_DISCRETE_Library.schlib; Mfr_name: YAGEO AMERICA; Mfr_part_number: RC0201JR-070RL; Mistral Part No: 110010070067-R; Package: 0201; Part_type: RESISTORS\FIXED; Project: PB_BUGBASE; RoHS: RoHS; Temperature: -55°C+125°C; Tolerance: 5%; Voltage: NA; Wattage: 1/20W; Weight: 0.17mg; Datasheet: Y:\MIS_DATABASE\DATASHEETS\RESISTORS\RCXXXXL-SER_MAR18.PDF
R236-R251 = RESISTOR: RES 1.1K 1/20W 1% 0201; Chkd/date: MAZHAR/121207; Crtd /date: USMAN/121207; Custom_Duty: 15%; Customs_HS_Code: 85332119; Distributor_name: DIGIKEY; Distributor_part_number: P1.10KABCT-ND; Footprint Path: Y:\MIS_DATABASE\Library\ALTIUM_TOOL\PCB_FOOTPRINTS\Altium_Footprint_Lib.PcbLib; Height: 0.26MM; Library Path: Y:\MIS_DATABASE\Library\ALTIUM_TOOL\SCHEMATICS_PARTS\MS_DISCRETE_Library.schlib; Mfr_name: PANASONIC-ECG; Mfr_part_number: ERJ-1GEF1101C; Mistral Part No: 110009030097-R; Package: 0201; Part_type: RESISTORS\FIXED; Project: SD_WATERLOO; RoHS: RoHS; Temperature: -55°C+125°C; Tolerance: 1%; Voltage: NA; Wattage: 1/20W; Weight: 0.15mg; Datasheet: Y:\MIS_DATABASE\DATASHEETS\RESISTORS\PAN-ERJSER_NOV17.PDF
R527 = RESISTOR: RES 1K 1/10W 1% 0402; Chkd/date: VASANTHA/281216; Crtd /date: MAZHAR/150506; Custom_Duty: 15%; Customs_HS_Code: 85332119; Distributor_name: DIGIKEY; Distributor_part_number: P1.00KLCT-ND; Footprint Path: Y:\MIS_DATABASE\Library\ALTIUM_TOOL\PCB_FOOTPRINTS\Altium_Footprint_Lib.PcbLib; Height: 0.40MM; Library Path: Y:\MIS_DATABASE\Library\ALTIUM_TOOL\SCHEMATICS_PARTS\MS_DISCRETE_Library.schlib; Mfr_name: PANASONIC-ECG; Mfr_part_number: ERJ-2RKF1001X; Mistral Part No: 110009030411-R; Package: 0402; Part_type: RESISTORS\FIXED; Project: VOCERA; RoHS: RoHS; Temperature: -55°C+155°C; Tolerance: 1%; Voltage: NA; Wattage: 1/10W; Weight: 0.8mg; Datasheet: Y:\MIS_DATABASE\DATASHEETS\RESISTORS\PAN-ERJSER_NOV17.PDF
SW1 SW2 = SW16_CHS-08A: SWITCH SLIDE SPST ST SMD; Chkd/date: MANIRAJA/051020; Crtd /date: ALVY/011020; Custom_Duty: 24%; Customs_HS_Code: 85369090; Distributor_name: DIGIKEY; Distributor_part_number: 732-3857-1-ND; Footprint Path: Y:\MIS_DATABASE\Library\ALTIUM_TOOL\PCB_FOOTPRINTS\Altium_Footprint_Lib.PcbLib; Height: 2.65MM; Library Path: Y:\MIS_DATABASE\Library\ALTIUM_TOOL\SCHEMATICS_PARTS\MS_SWITCH_Library.schlib; Mfr_name: WURTH ELECTRONICS; Mistral Part No: 130020100001-R; Package: SMD; Part_type: ELECTRO-MECHANICAL\SWITCH; Project: AM64X_SKEVM; RoHS: RoHS; Temperature: -40°C+85°C; Tolerance: NA; Voltage: NA; Wattage: NA; Weight: 281.7mg; Datasheet: Y:\MIS_DATABASE\DATASHEETS\MISC\SWITCHES\4161311608XX.PDF
U43 = SN74LVC1G08DBVRE4_SOT23-5: IC SINGLE 2-INPUT POSITIVE AND GATE SOT23-5; Chkd/date: SUHAS/221010; Crtd /date: USMAN/151008; Custom_Duty: 15%; Customs_HS_Code: 85423100; Distributor_name: DIGIKEY; Distributor_part_number: SN74LVC1G08DBVRE4-ND; Height: 1.45MM; Mfr_name: TEXAS INSTRUMENTS; Mistral Part No: 141009060026-R; Part_type: ICS\DIGITAL\GATES; Project: KHAN_MAIN; RoHS: Sb/ Br FREE; Temperature: -40°C+85°C; Datasheet: Y:\MIS_DATABASE\DATASHEETS\ICS\DIGITAL\GATES\SN74LVC1G08.PDF
U73 U75 = SN74AVC8T245RHL_QFN24: IC BUS TRANSCEIVER 8-BIT DUAL-SUPPLY QFN24; Chkd/date: VASANTHA/231216; Crtd /date: BAVISH/290411; Custom_Duty: 15%; Customs_HS_Code: 85423100; Distributor_name: DIGIKEY; Distributor_part_number: 296-17859-1-ND; Height: 1.00MM; Mfr_name: TEXAS INSTRUMENTS; Mfr_part_number: SN74AVC8T245RHLR; Mistral Part No: 143011040001-R; Package: QFN24; Part_type: ICS\TELECOM\TRANSCEIVER; Project: OMAPL1_PEC20; RoHS: RoHS; Temperature: -40°C+85°C; Tolerance: NA; Voltage: NA; Wattage: NA; Weight: NA; Datasheet: Y:\MIS_DATABASE\DATASHEETS\ICS\DIGITAL\BUSTRANSCEIVER\SN74AVC8T245.PDF
U74 = TCA6424ARGJR_QFN32: IC I2C I/O EXPANDER 24B UQFN32; Chkd/date: NAVEED/100715; Crtd /date: NAVEED/100914; Custom_Duty: 15%; Customs_HS_Code: 85423100; Distributor_name: DIGIKEY; Distributor_part_number: 296-27844-1-ND; Height: 0.60MM; Mfr_name: TEXAS INSTRUMENTS; Mistral Part No: 141014090009-R; Package: UQFN32; Part_type: ICS\DIGITAL\BUSTRANSCEIVER; Project: ZK_BIOMETRIC; RoHS: RoHS; Temperature: -40°C+85°C; Weight: NA; Datasheet: Y:\MIS_DATABASE\DATASHEETS\ICS\DIGITAL\BUSTRANSCEIVER\TCA6424AR.PDF
U12 = AM62-EVM_BGA425: IC AM62 SoC MICROPROCESSOR BGA425; Chkd/date: ALVY/110621; Crtd /date: MANIRAJA/110621; Custom_Duty: 15%; Customs_HS_Code: 85423100; Distributor_name: NA; Distributor_part_number: NA; Footprint Path: Y:\MIS_DATABASE\Library\ALTIUM_TOOL\PCB_FOOTPRINTS\Altium_Footprint_Lib.PcbLib; Height: 0.65MM; Library Path: Y:\MIS_DATABASE\Library\ALTIUM_TOOL\SCHEMATICS_PARTS\MS_MICROPROCESSOR_Library.schlib; Mfr_name: TEXAS INSTRUMENTS; Mistral Part No: 141221060001; Package: BGA425; Part_type: ICS\DIGITAL\MICROPROCESSOR; Project: AM62_EVM_BRD; RoHS: NA; Temperature: NA; Tolerance: NA; Voltage: NA; Wattage: NA; Weight: NA; Datasheet: Y:\MIS_DATABASE\DATASHEETS\ICS\DIGITAL\MICROCONTROLLER\AM62-SoC_SVB.PDF

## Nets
DGND: C159.2 C166.2 C167.2 C322.2 C324.1 C325.1 C326.1 C375.2 C430.1 C431.2 C439.1 C440.2 C442.1 C474.2 C477.2 J23.7 J23.16 J23.25 J23.34 J23.40 J23.41 J23.42 R160.2 R162.2 R169.2 R202.2 R203.2 R204.2 R205.2 R206.2 R207.2 R208.2 R209.2 R210.2 R211.2 R212.2 R213.2 R214.2 R215.2 R216.2 R217.2 R252.1 R368.1 R521.2 R527.1 R712.1 U38.8(~{G}) U38.16(GND) U42.4(GND) U43.3(GND) U52.4(GND) U73.11(GND1) U73.12(GND2) U73.13(GND3) U73.25(EP) U74.25(GND) U74.33(EP) U75.11(GND1) U75.12(GND2) U75.13(GND3) U75.25(EP) ; also on sheet 1 10 11 12 13 14 15 16 17 18 19 20 21 22 23 24 28 29 30 31 32 33 34 35 36 37 38 39 40 41 42 43
VCC1V8_CLKBUF: C324.2 C325.2 C326.2 FL22.2 R380.2 U52.6(VDD) ; also on sheet 42
VCC3V3_TA: C166.1 C167.1 C430.2 C439.2 C442.2 C474.1 C477.1 J23.1 J23.2 J23.3 R218.1 R236.2 R237.2 R238.2 R239.2 R240.2 R241.2 R242.2 R243.2 R244.2 R245.2 R246.2 R247.2 R248.2 R249.2 R250.2 R251.2 R498.1 R499.1 R514.2 R517.2 R522.2 R566.2 R567.2 R568.2 R581.1 R582.1 R585.2 R586.2 R587.2 R600.1 U42.8(VCCB) U43.5(VCC) U73.1(VCCA) U74.27(VCCP) U74.31(VCC) U75.1(VCCA) ; also on sheet 1
VCC_1V8: FL22.1 ; also on sheet 12 13 14 18 19 21 34 37 39 40 42
VCC_3V3_MAIN: R582.2 ; also on sheet 12 13 15
VCC_3V3_SYS: C159.1 C375.1 C431.1 C440.1 R159.1 R161.1 R166.1 R167.1 R168.1 R170.1 R171.1 R175.1 U38.1(VCC) U42.1(VCCA) U73.23(VCCB1) U73.24(VCCB2) U75.23(VCCB1) U75.24(VCCB2) ; also on sheet 10 12 13 14 18 19 20 22 23 24 29 30 31 32 33 34 35 36 37 38 39 40 41 42 43
BOOTMODE0: U75.14(B8) ; also on sheet 32
BOOTMODE1: U75.15(B7) ; also on sheet 32
BOOTMODE2: U75.16(B6) ; also on sheet 32
BOOTMODE3: U75.17(B5) ; also on sheet 32
BOOTMODE4: U75.18(B4) ; also on sheet 32
BOOTMODE5: U75.19(B3) ; also on sheet 32
BOOTMODE6: U75.20(B2) ; also on sheet 32
BOOTMODE7: U75.21(B1) ; also on sheet 32
BOOTMODE8: U73.14(B8) ; also on sheet 32
BOOTMODE9: U73.15(B7) ; also on sheet 32
BOOTMODE10: U73.16(B6) ; also on sheet 32
BOOTMODE11: U73.17(B5) ; also on sheet 32
BOOTMODE12: U73.18(B4) ; also on sheet 32
BOOTMODE13: U73.19(B3) ; also on sheet 32
BOOTMODE14: U73.20(B2) ; also on sheet 32
BOOTMODE15: U73.21(B1) ; also on sheet 32
BOOTMODE_I2C_SCL: R589.1 R600.2 TP83.1(TP) U74.29(SCL) ; also on sheet 1
BOOTMODE_I2C_SDA: R581.2 R591.1 TP84.1(TP) U74.30(SDA) ; also on sheet 1
BOOTMODEON: R252.2 U43.4(Y) U73.22(~{OE}) U75.22(~{OE})
CLKOUT0: U52.1(CLKIN) ; also on sheet 42
CPSW_RGMII1_ETH1_CLK: R382.2 ; also on sheet 23
CPSW_RGMII1_RD0: U12.AB17(RGMII1_RD0) ; also on sheet 23
CPSW_RGMII1_RD1: U12.AC17(RGMII1_RD1) ; also on sheet 23
CPSW_RGMII1_RD2: U12.AB16(RGMII1_RD2) ; also on sheet 23
CPSW_RGMII1_RD3: U12.AA15(RGMII1_RD3) ; also on sheet 23
CPSW_RGMII1_RX_CTL: U12.AE17(RGMII1_RX_CTL) ; also on sheet 23
CPSW_RGMII1_RXC: U12.AD17(RGMII1_RXC) ; also on sheet 23
CPSW_RGMII1_TD0: U12.AE20(RGMII1_TD0) ; also on sheet 23
CPSW_RGMII1_TD1: U12.AD20(RGMII1_TD1) ; also on sheet 23
CPSW_RGMII1_TD2: U12.AE18(RGMII1_TD2) ; also on sheet 23
CPSW_RGMII1_TD3: U12.AD18(RGMII1_TD3) ; also on sheet 23
CPSW_RGMII1_TX_CTL: U12.AD19(RGMII1_TX_CTL) ; also on sheet 23
CPSW_RGMII1_TXC: R360.2 ; also on sheet 23
CPSW_RGMII2_ETH2_CLK: R369.2 ; also on sheet 24
CPSW_RGMII2_RD0: U12.AE23(RGMII2_RD0) ; also on sheet 24
CPSW_RGMII2_RD1: U12.AB20(RGMII2_RD1) ; also on sheet 24
CPSW_RGMII2_RD2: U12.AC21(RGMII2_RD2) ; also on sheet 24
CPSW_RGMII2_RD3: U12.AE22(RGMII2_RD3) ; also on sheet 24
CPSW_RGMII2_RX_CTL: U12.AD22(RGMII2_RX_CTL) ; also on sheet 24
CPSW_RGMII2_RXC: U12.AD23(RGMII2_RXC) ; also on sheet 24
CPSW_RGMII2_TD0: U12.Y18(RGMII2_TD0) ; also on sheet 24
CPSW_RGMII2_TD1: U12.AA18(RGMII2_TD1) ; also on sheet 24
CPSW_RGMII2_TD2: U12.AD21(RGMII2_TD2) ; also on sheet 24
CPSW_RGMII2_TD3: U12.AC20(RGMII2_TD3) ; also on sheet 24
CPSW_RGMII2_TX_CTL: U12.AA19(RGMII2_TX_CTL) ; also on sheet 24
CPSW_RGMII2_TXC: R65.2 ; also on sheet 24
DIR: R514.1 U73.2(DIR) U75.2(DIR)
IO_EXP_ADDR: R521.1 U74.26(ADDR)
LED1: LD9.1(CATHODE) U38.3(DRAIN0)
LED2: LD8.1(CATHODE) U38.4(DRAIN1)
LED3: LD7.1(CATHODE) U38.5(DRAIN2)
LED4: LD6.1(CATHODE) U38.6(DRAIN3)
LED5: LD2.1(CATHODE) U38.11(DRAIN4)
LED6: LD3.1(CATHODE) U38.12(DRAIN5)
LED7: LD4.1(CATHODE) U38.13(DRAIN6)
LED8: LD5.1(CATHODE) U38.14(DRAIN7)
PORz_OUT: R221.2 ; also on sheet 20 23 24 42
RESETSTATz: R222.2 ; also on sheet 13 19 20 21 23 24 32 33 37 39 40 41 42
SoC_CLKIN: C322.1 R368.2 R372.2 ; also on sheet 34
SOC_I2C1_SCL: U42.2(SCLA) ; also on sheet 14 22 39 40 41 42
SOC_I2C1_SDA: U42.3(SDAA) ; also on sheet 14 22 39 40 41 42
SoC_I2C1_TA_SCL: R499.2 R583.1 U42.7(SCLB) ; also on sheet 1
SoC_I2C1_TA_SDA: R498.2 R590.1 U42.6(SDAB) ; also on sheet 1
SYS_BOOTMODE0: R202.1 SW1.1 U74.1(P00) U75.10(A8)
SYS_BOOTMODE1: R203.1 SW1.2 U74.2(P01) U75.9(A7)
SYS_BOOTMODE2: R204.1 SW1.3 U74.3(P02) U75.8(A6)
SYS_BOOTMODE3: R205.1 SW1.4 U74.4(P03) U75.7(A5)
SYS_BOOTMODE4: R206.1 SW1.5 U74.5(P04) U75.6(A4)
SYS_BOOTMODE5: R207.1 SW1.6 U74.6(P05) U75.5(A3)
SYS_BOOTMODE6: R208.1 SW1.7 U74.7(P06) U75.4(A2)
SYS_BOOTMODE7: R209.1 SW1.8 U74.8(P07) U75.3(A1)
SYS_BOOTMODE8: R210.1 SW2.1 U73.10(A8) U74.9(P10)
SYS_BOOTMODE9: R211.1 SW2.2 U73.9(A7) U74.10(P11)
SYS_BOOTMODE10: R212.1 SW2.3 U73.8(A6) U74.11(P12)
SYS_BOOTMODE11: R213.1 SW2.4 U73.7(A5) U74.12(P13)
SYS_BOOTMODE12: R214.1 SW2.5 U73.6(A4) U74.13(P14)
SYS_BOOTMODE13: R215.1 SW2.6 U73.5(A3) U74.14(P15)
SYS_BOOTMODE14: R216.1 SW2.7 U73.4(A2) U74.15(P16)
SYS_BOOTMODE15: R217.1 SW2.8 U73.3(A1) U74.16(P17)
SYSBOOT_BUF_ENz: R221.1 R222.1 U43.1(A)
TCA6424_EXP_INT: R522.1 U74.32(~{INT})
TEST_GPIO1: R587.1 R596.1 ; also on sheet 1 43
TEST_GPIO2: R567.1 R571.1 TP117.1(TP) ; also on sheet 1
TEST_GPIO3: J14.1 R517.1 R597.1 TP73.1(TP) U43.2(B) ; also on sheet 1
TEST_GPIO4: R568.1 R569.1 TP74.1(TP) U74.28(~{RESET}) ; also on sheet 1
TEST_PORZn: R586.1 R595.1 ; also on sheet 1 42
TEST_POWERDOWN: R585.1 R594.1 ; also on sheet 1 13
TEST_WARMRESETn: R566.1 R570.1 ; also on sheet 1 43
WKUP_I2C0_SCL: U38.15(SCL) ; also on sheet 32
WKUP_I2C0_SDA: U38.2(SDA) ; also on sheet 32
N16943223: R380.1 U52.2(1G)
N16943354: R372.1 U52.3(Y0)
N16943356: R382.1 U52.8(Y1)
N16943358: R369.1 U52.5(Y2)
N16944070: R360.1 U12.AE19(RGMII1_TXC)
N16944341: R65.1 U12.AE21(RGMII2_TXC)
N16944941: LD9.2(ANODE) R175.2
N16944943: LD8.2(ANODE) R171.2
N16944955: LD7.2(ANODE) R170.2
N16944965: LD6.2(ANODE) R168.2
N16944969: LD2.2(ANODE) R159.2
N16944978: LD3.2(ANODE) R161.2
N16944987: LD4.2(ANODE) R166.2
N16944997: LD5.2(ANODE) R167.2
N16945140: R169.1 U38.7(A2)
N16945144: R162.1 U38.10(A1)
N16945148: R160.1 U38.9(A0)
N16990175: J23.27 R595.2
N16990176: J23.30 R596.2
N16990179: J23.31 R571.2
N16990180: J23.32 R597.2
N16990246: J23.26 R594.2
N16990247: J23.28 R570.2
N16990252: J23.33 R569.2
N17078351: R239.1 SW1.13
N17078353: R238.1 SW1.14
N17078355: R237.1 SW1.15
N17078357: R236.1 SW1.16
N17078758: R249.1 SW2.11
N17078760: R248.1 SW2.12
N17078762: R247.1 SW2.13
N17078764: R246.1 SW2.14
N17078766: R251.1 SW2.9
N17078768: R250.1 SW2.10
N17078770: R245.1 SW2.15
N17078778: R244.1 SW2.16
N17078974: J14.2 R527.2
N17084256: R243.1 SW1.9
N17084257: R242.1 SW1.10
N17084258: R241.1 SW1.11
N17084259: R240.1 SW1.12
N18374804: J23.36 R583.2
N18374807: J23.37 R589.2
N18374810: J23.38 R590.2
N18374813: J23.39 R591.2
N20607945: R218.2 R712.2 U42.5(EN)

Not connected (* = marked no-connect by the designer): J23 4* 5* 6* 8* 9* 10* 11* 12* 13* 14* 15* 17* 18* 19* 20* 21* 22* 23* 24* 29* 35*; U52 7(NC)*; U74 17(P20)* 18(P21)* 19(P22)* 20(P23)* 21(P24)* 22(P25)* 23(P26)* 24(P27)*

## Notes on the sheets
sheet 25
- SOC MAC INTERFACE
- CLOCK BUFFER FOR SOC AND ETHERNET PHYs
- D-Note :-
  Add an additional bulk cap
- D-Note:-
  C and R must be DNI.
  Mounting these components
  affects the  output clock
  amplitude and
  board performance.
- D-Note :-
  Add series resistors 22 R on the Ethernet
  interface TX (TDx) signals near to the SoC
- LED DRIVER
- GREEN
- RED
- GREEN
- AMBER
- GREEN
- RED
- GREEN
- AMBER
- I2C ADDRESS: 0x60
sheet 26
- 40-PIN TEST AUTOMATION HEADER
- I2C BUS BUFFER
- D-Note :-
  Refer AM62P test automation
  implementation for the latest
  updates
- Silk: AUTOMATION HDR
- TEST AUTOMATION GPIO MAPPING
- Internal/
  External
  PU/PD states
- SIGNAL NAME
- DESCRIPTION
- Direction WRT CTRL
- OUTPUT
  OUTPUT
  OUTPUT
  OUTPUT
  OUTPUT
  OUTPUT
  OUTPUT
- TEST_POWERDOWN
  TEST_PORZn
  TEST_WARMRESETn
  TEST_GPIO1
  TEST_GPIO2
  TEST_GPIO3
  TEST_GPIO4
- Used to Power down the EVM
  Used to  Reset the SoC PORz
  Used to Reset the SoC Warmreset
  Used to Generate the interrupt on
  MCU_GPIO0_15 Pin
  Connected to a Testpoint
  Used to Enable the BOOTMODE Buffer
  Used to Reset the Bootmode I2C IO Expander
- External Pullup
  External Pullup
  External Pullup
  External Pullup
  External Pullup
  External Pullup
  External Pullup
sheet 27
- BOOT MODE BUFFERS
- BOOTMODE IO EXPANDER
- D-Note
  Add additional decap
  Verify and terminate unused IOs
- D-Note :-
  Bootmode buffers are optional
  for the custom board
- DIR = H: A -> B
  DIR = L: B -> A
  OE = H: output = Hi-Z
- DIR = H: A -> B
  DIR = L: B -> A
  OE = H: output = Hi-Z
- I2C ADDRESS: 0x22
- BOOTMODE CONFIGURATION RESISTORS
          AND BOOTMODE SWITCHES
- D-Note :-
  VCC3V3_XDS_TA supply is used to
  support test automation.
  Connect SoC_DVDD3V3 in the custom
  board design when buffers are not used
- D-Note :-
  it is not recommended to leave any of
  the the bootmode pin open including
  reserved pins
- D-Note :-
  Dip switch is optional and used on the SK for ease of configuration
  A pullup or pulldown resistor can be used to set the BOOTMODE configuration
  Provide provision for Pullup and Pulldown resistors for the bootmode pins
  that have configuration capability
- SWITCH ON  =  LOGIC 1
  SWITCH OFF =  LOGIC 0
- BOOT MODES SUPPORTED
- 1. OSPI
- Silk: BMODE 0-7
- Silk: BMODE 8-15
- 2. MMC1 - SD CARD
- 3. UART
- 4. eMMC
- 5. BACKUP BOOT OPTION
- D-Note :-
  When dip switches are used on custom
  board, an external ESD protection may
  be required if the DIP switches are
  expected to be configured in an
  uncontrolled ESD environment
- D-Note :-
  When DIP switches are used, reduce the
  resistor values used for the divider to
  47K and 470R maintaining the ratio
